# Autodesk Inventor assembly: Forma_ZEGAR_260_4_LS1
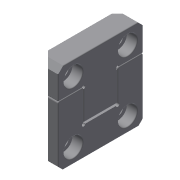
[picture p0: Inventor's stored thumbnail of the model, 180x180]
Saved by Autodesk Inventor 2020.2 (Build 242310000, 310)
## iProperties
Created: 2015-01
Part Number: Forma_ZEGAR_260_4_LS1
Document SubType Name: Assembly
Designer: F.Stasiak
Catalog Web Link: www.expertbooks.pl
Manager: www.cadconsulting.pl
Company: Fabian Stasiak CAD Consulting
Author: F.Stasiak
Subject: Zbiór ćwiczeń. Autodesk Inventor 2020. Kurs Professional
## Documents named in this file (3)
- C:\2020_Kurs_Professional\R6 Formy\Komponenty\LS\DME_FW45 1\Forma_ZEGAR_260_4_LS1.iam
- C:\2020_Kurs_Professional\R6 Formy\Komponenty\LS\DME_FW45 1\Forma_ZEGAR_260_4_LS1_FW45_F.ipt
- C:\2020_Kurs_Professional\R6 Formy\Komponenty\LS\DME_FW45 1\Forma_ZEGAR_260_4_LS1_FW45_M.ipt
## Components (2 placed, 2 different names)
1. Forma_ZEGAR_260_4_LS1_FW45_F:1 — Równoległy:1, Równoległy:2, Równoległy:3
2. Forma_ZEGAR_260_4_LS1_FW45_M:1 — Równoległy:1, Równoległy:2, Równoległy:3, Równoległy:4, Równoległy:5, Równoległy:6
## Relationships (6: Flush 6)
- Równoległy:1 [Flush]: Forma_ZEGAR_260_4_LS1_FW45_F:1 ↔ Forma_ZEGAR_260_4_LS1_FW45_M:1
- Równoległy:2 [Flush]: Forma_ZEGAR_260_4_LS1_FW45_F:1 ↔ Forma_ZEGAR_260_4_LS1_FW45_M:1
- Równoległy:3 [Flush]: Forma_ZEGAR_260_4_LS1_FW45_F:1 ↔ Forma_ZEGAR_260_4_LS1_FW45_M:1
- Równoległy:4 [Flush]: Forma_ZEGAR_260_4_LS1_FW45_M:1
- Równoległy:5 [Flush]: Forma_ZEGAR_260_4_LS1_FW45_M:1
- Równoległy:6 [Flush]: Forma_ZEGAR_260_4_LS1_FW45_M:1
